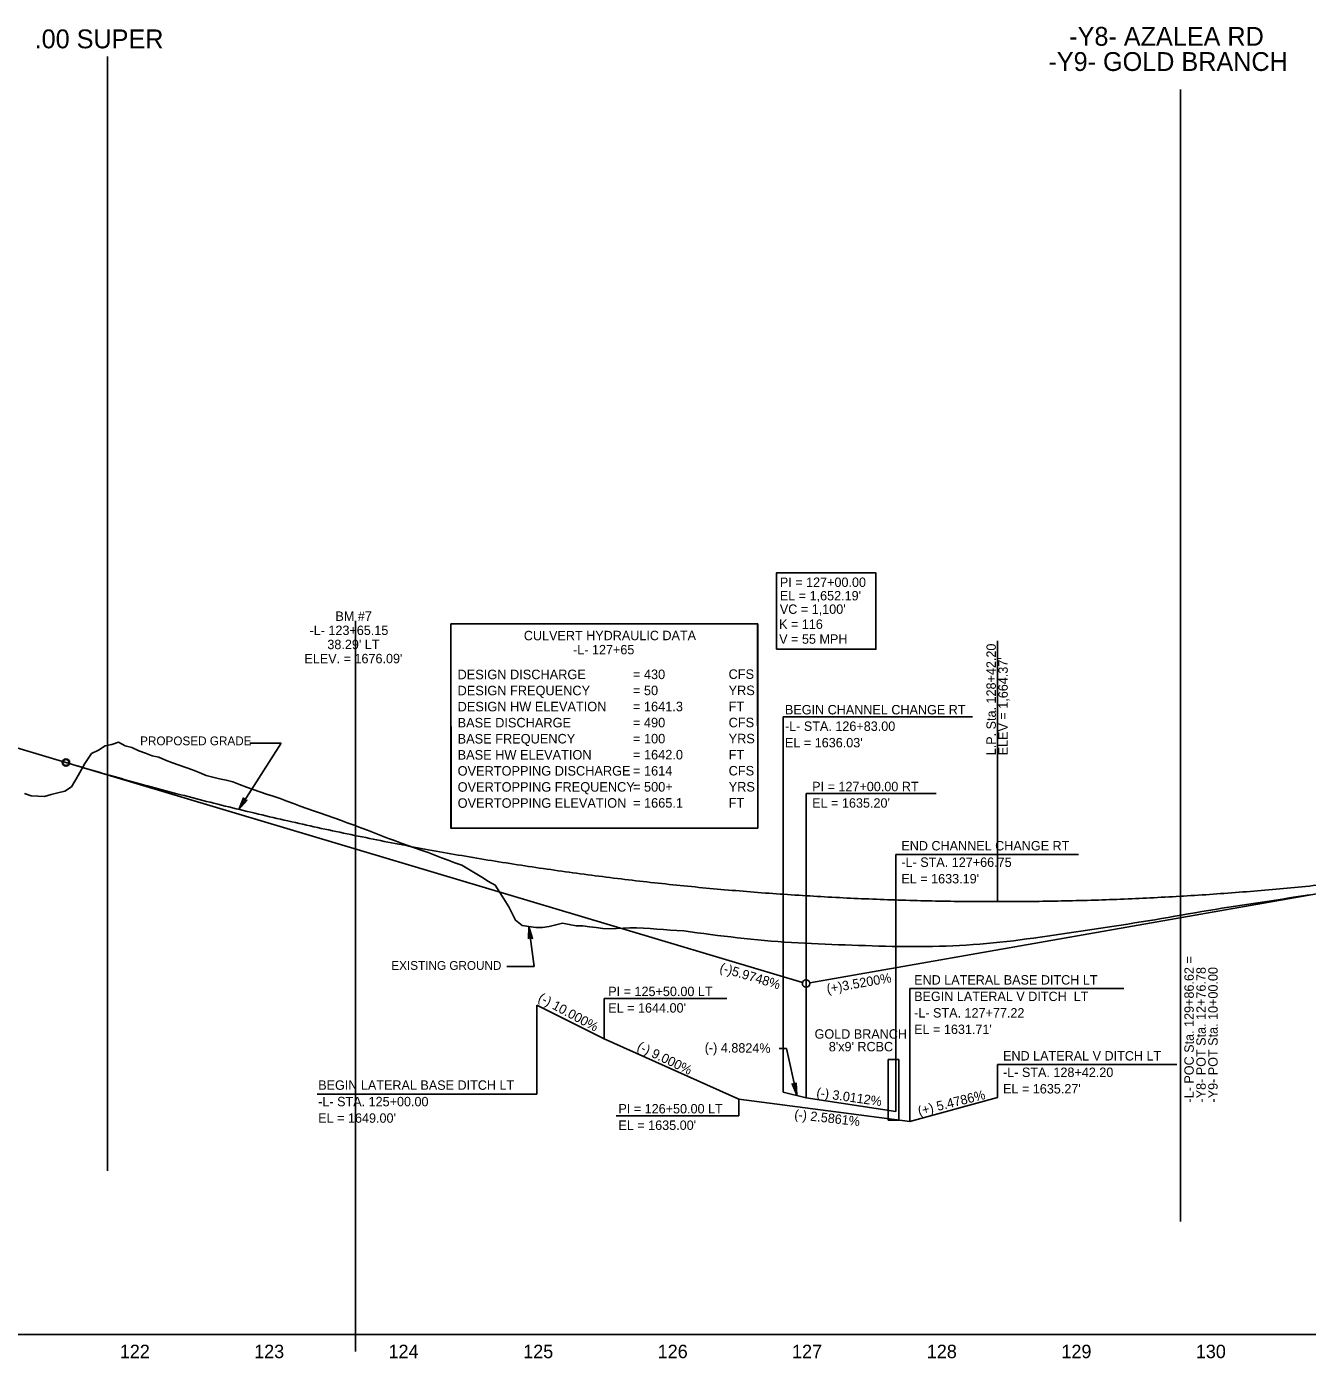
# Model space of a CAD drawing. Extents: x 498575 to 532350, y 405181 to 484585.
# Drawn here: x 516940 to 517892, y 483216 to 484206 of the extents above; entities that cross this region are included whole.
import ezdxf

# ---------------------------------------------------------------- set-up
doc = ezdxf.new("R2010")
doc.units = 0
for name, color, linetype in [('Default', 7, 'Continuous'), ('Exist Profile Cell', 7, 'Continuous'), ('Exist Vertical Profile Ground Line', 7, 'Continuous'), ('Exist Vertical Profile Horizontal Axis Label Major', 7, 'Continuous'), ('Prop Grid Mask', 7, 'Continuous'), ('Prop PFL Text', 7, 'Continuous'), ('Prop Roadway Culvert', 7, 'Continuous'), ('Prop Vertical Profile Curve Label', 7, 'Continuous'), ('Prop Vertical Profile Ditch Grade Left', 7, 'Continuous'), ('Prop Vertical Profile Ditch Grade Left Label', 7, 'Continuous'), ('Prop Vertical Profile Ditch Grade Right', 7, 'Continuous'), ('Prop Vertical Profile Ditch Grade Right Label', 7, 'Continuous'), ('Prop Vertical Profile Grade', 7, 'Continuous'), ('Prop Vertical Profile Grade Label', 7, 'Continuous'), ('Prop Vertical Profile Strip Grade', 7, 'Continuous'), ('Prop VPI Label', 7, 'Continuous'), ('Scratch_Level_0', 7, 'Continuous'), ('Scratch_Level_2', 7, 'Continuous'), ('Scratch_Level_4', 7, 'Continuous')]:
    doc.layers.add(name, color=color, linetype=linetype)

msp = doc.modelspace()

# ---------------------------------------------------------------- linework, layer by layer
at = {"layer": 'Exist Profile Cell'}
msp.add_line((505856.74, 483233.71), (526056.74, 483233.71), dxfattribs=at)
at = {"layer": 'Exist Vertical Profile Ground Line'}
for points in [[(516938.15, 483635.91), (516943.15, 483634.26), (516948.15, 483633.98), (516953.15, 483633.65), (516958.15, 483635.29), (516963.15, 483636.53), (516968.15, 483637.76), (516973.15, 483640.98), (516978.15, 483649.41), (516983.15, 483658.36), (516988.15, 483665.73), (516993.15, 483668.28), (516998.15, 483671.49), (517003.15, 483672.43), (517008.15, 483674.15), (517013.15, 483671.33), (517018.15, 483670.07), (517023.15, 483667.74), (517028.15, 483665.91), (517033.15, 483664.04), (517038.15, 483662.85), (517043.15, 483660.68), (517048.15, 483658.81), (517053.15, 483657.04), (517058.15, 483655.3), (517063.15, 483653.64), (517068.15, 483651.49), (517073.15, 483649.32), (517078.15, 483648.08), (517083.15, 483646.97), (517088.15, 483645.87), (517093.15, 483644.6), (517098.15, 483642.68), (517103.15, 483640.79), (517108.15, 483638.94), (517113.15, 483637.09), (517118.15, 483635.44), (517123.15, 483633.91), (517128.15, 483632.2), (517133.15, 483630.34), (517138.15, 483628.51), (517143.15, 483626.66), (517148.15, 483624.83), (517153.15, 483623.13), (517158.15, 483621.3), (517163.15, 483619.66), (517168.15, 483617.92), (517173.15, 483616.15), (517178.15, 483614.26), (517183.15, 483612.39), (517188.15, 483610.51), (517193.15, 483608.58), (517198.15, 483606.7), (517203.15, 483604.78), (517208.15, 483602.79), (517213.15, 483600.9), (517218.15, 483598.93), (517223.15, 483597.36), (517228.15, 483595.45), (517233.15, 483593.72), (517238.15, 483592.01), (517243.15, 483590.06), (517248.15, 483588.18), (517253.15, 483586.38), (517258.15, 483584.54), (517263.15, 483582.71), (517268.15, 483579.74), (517273.15, 483576.76), (517278.15, 483573.67), (517283.15, 483570.65), (517288.15, 483567.89), (517293.15, 483559.75), (517298.15, 483551.63), (517303.15, 483541.76), (517308.15, 483537.89), (517313.15, 483537)], [(517813.15, 483548.19), (517818.15, 483549.01), (517823.15, 483549.8), (517828.15, 483550.61), (517833.15, 483551.38), (517838.15, 483552.16), (517843.15, 483552.92), (517848.15, 483553.69), (517853.15, 483554.44), (517858.15, 483555.23), (517863.15, 483555.99), (517868.15, 483556.77), (517873.15, 483557.51), (517878.15, 483558.3), (517883.15, 483559.07), (517888.15, 483559.85), (517893.15, 483560.6)], [(517313.15, 483537), (517318.15, 483536.34), (517323.15, 483536.41), (517328.15, 483537.05), (517333.15, 483538.23), (517338.15, 483539.57), (517343.15, 483538.69), (517348.15, 483537.64), (517353.15, 483537.55), (517358.15, 483536.92), (517363.15, 483536.25), (517368.15, 483535.55), (517373.15, 483535.33), (517378.15, 483535.61), (517383.15, 483535.86), (517388.15, 483536.06), (517393.15, 483536.18), (517398.15, 483535.78), (517403.15, 483535.51), (517408.15, 483535.23), (517413.15, 483534.93), (517418.15, 483534.39), (517423.15, 483534.12), (517428.15, 483533.87), (517433.15, 483533.19), (517438.15, 483532.49), (517443.15, 483531.79), (517448.15, 483531.08), (517453.15, 483530.44), (517458.15, 483529.91), (517463.15, 483529.32), (517468.15, 483528.69), (517473.15, 483528.11), (517478.15, 483527.57), (517483.15, 483527.08), (517488.15, 483526.61), (517493.15, 483526.2), (517498.15, 483525.89), (517503.15, 483525.51), (517508.15, 483525.2), (517513.15, 483524.9), (517518.15, 483524.63), (517523.15, 483524.38), (517528.15, 483524.18), (517533.15, 483523.98), (517538.15, 483523.77), (517543.15, 483523.58), (517548.15, 483523.37), (517553.15, 483523.19), (517558.15, 483523.02), (517563.15, 483522.88), (517568.15, 483522.73), (517573.15, 483522.54), (517578.15, 483522.42), (517583.15, 483522.31), (517588.15, 483522.23), (517593.15, 483522.18), (517598.15, 483522.15), (517603.15, 483522.17), (517608.15, 483522.23), (517613.15, 483522.3), (517618.15, 483522.42), (517623.15, 483522.55), (517628.15, 483522.77), (517633.15, 483523.01), (517638.15, 483523.33), (517643.15, 483523.66), (517648.15, 483524.04), (517653.15, 483524.47), (517658.15, 483524.89), (517663.15, 483525.39), (517668.15, 483525.94), (517673.15, 483526.54), (517678.15, 483527.16), (517683.15, 483527.82), (517688.15, 483528.49), (517693.15, 483529.18), (517698.15, 483529.86), (517703.15, 483530.57), (517708.15, 483531.31), (517713.15, 483532.04), (517718.15, 483532.8), (517723.15, 483533.52), (517728.15, 483534.28), (517733.15, 483535.05), (517738.15, 483535.83), (517743.15, 483536.63), (517748.15, 483537.42), (517753.15, 483538.16), (517758.15, 483538.94), (517763.15, 483539.72), (517768.15, 483540.5), (517773.15, 483541.3), (517778.15, 483542.15), (517783.15, 483543), (517788.15, 483543.86), (517793.15, 483544.73), (517798.15, 483545.61), (517803.15, 483546.46), (517808.15, 483547.33), (517813.15, 483548.19)]]:
    msp.add_lwpolyline(points, dxfattribs=at)
at = {"layer": 'Prop Grid Mask'}
for points in [[(517497.03, 483743.2), (517571.01, 483743.2), (517571.01, 483799.98), (517497.03, 483799.98)], [(517255.18, 483762.06), (517483.11, 483762.06), (517483.11, 483610.19), (517255.18, 483610.19)], [(517255.3, 483610.01), (517483.11, 483610.19), (517482.99, 483762.06), (517255.18, 483761.88)]]:
    msp.add_lwpolyline(points, close=True, dxfattribs=at)
at = {"layer": 'Prop PFL Text'}
for p, q in [((517097.6, 483624.14), (517129.13, 483673.33)), ((517129.13, 483673.33), (517105.71, 483673.33)), ((517317.11, 483507.41), (517312.98, 483537.03)), ((517296.75, 483507.41), (517317.11, 483507.41))]:
    msp.add_line(p, q, dxfattribs=at)
for points in [[(517103.71, 483630.92), (517097.6, 483624.14), (517101.07, 483632.65), (517101.81, 483630.82)], [(517312.69, 483527.9), (517312.98, 483537.03), (517315.82, 483528.29), (517314.08, 483529.21)]]:
    msp.add_lwpolyline(points, close=True, dxfattribs=at)
at = {"layer": 'Prop Roadway Culvert'}
for p, q in [((517580.08, 483393.16), (517580.08, 483438.16)), ((517580.08, 483438.16), (517588.08, 483438.16)), ((517588.08, 483393.16), (517588.08, 483438.16)), ((517580.08, 483393.16), (517588.08, 483393.16))]:
    msp.add_line(p, q, dxfattribs=at)
at = {"layer": 'Prop Vertical Profile Curve Label'}
msp.add_circle((516969.08, 483658.97), 2.25, dxfattribs=at)
at = {"layer": 'Prop Vertical Profile Ditch Grade Left'}
msp.add_lwpolyline([(517319.08, 483478.71), (517369.08, 483453.71), (517469.08, 483408.71), (517596.3, 483392.26), (517661.28, 483410.06)], dxfattribs=at)
at = {"layer": 'Prop Vertical Profile Ditch Grade Left Label'}
for p, q in [((517369.08, 483453.71), (517369.08, 483483.62)), ((517460.19, 483483.62), (517369.08, 483483.62)), ((517596.3, 483392.26), (517596.3, 483491.03)), ((517755.25, 483491.03), (517596.3, 483491.03)), ((517319.08, 483478.71), (517319.08, 483412.56)), ((517661.28, 483410.06), (517661.28, 483434.63)), ((517794.7, 483434.63), (517661.28, 483434.63)), ((517155.76, 483412.56), (517319.08, 483412.56)), ((517469.08, 483408.71), (517469.08, 483396.42)), ((517469.08, 483396.42), (517377.96, 483396.42))]:
    msp.add_line(p, q, dxfattribs=at)
at = {"layer": 'Prop Vertical Profile Ditch Grade Right'}
msp.add_lwpolyline([(517502.08, 483413.86), (517519.08, 483409.71), (517585.83, 483399.66)], dxfattribs=at)
at = {"layer": 'Prop Vertical Profile Ditch Grade Right Label'}
for p, q in [((517502.08, 483413.86), (517502.08, 483692.83)), ((517642.75, 483692.83), (517502.08, 483692.83)), ((517519.08, 483409.71), (517519.08, 483635.91)), ((517615.72, 483635.91), (517519.08, 483635.91)), ((517721.5, 483590.68), (517585.83, 483590.68)), ((517585.83, 483399.66), (517585.83, 483590.68)), ((517504.61, 483446.41), (517499.12, 483446.41)), ((517504.61, 483446.41), (517512.1, 483411.64))]:
    msp.add_line(p, q, dxfattribs=at)
msp.add_lwpolyline([(517511.72, 483420.77), (517512.1, 483411.64), (517508.63, 483420.15), (517510.43, 483419.37)], close=True, dxfattribs=at)
at = {"layer": 'Prop Vertical Profile Grade'}
msp.add_line((516294.08, 483860.62), (516969.08, 483658.97), dxfattribs=at)
msp.add_spline([(516969.08, 483658.97), (516991.08, 483652.5), (517013.08, 483646.24), (517035.08, 483640.19), (517057.08, 483634.35), (517079.08, 483628.72), (517101.08, 483623.29), (517123.08, 483618.08), (517145.08, 483613.07), (517167.08, 483608.28), (517189.08, 483603.69), (517211.08, 483599.31), (517233.08, 483595.14), (517255.08, 483591.18), (517277.08, 483587.43), (517299.08, 483583.88), (517321.08, 483580.55), (517343.08, 483577.42), (517365.08, 483574.51), (517387.08, 483571.8), (517409.08, 483569.3), (517431.08, 483567.01), (517453.08, 483564.93), (517475.08, 483563.06), (517497.08, 483561.39), (517519.08, 483559.94), (517541.08, 483558.69), (517563.08, 483557.66), (517585.08, 483556.83), (517607.08, 483556.21), (517629.08, 483555.8), (517651.08, 483555.6), (517673.08, 483555.61), (517695.08, 483555.82), (517717.08, 483556.25), (517739.08, 483556.88), (517761.08, 483557.72), (517783.08, 483558.78), (517805.08, 483560.04), (517827.08, 483561.51), (517849.08, 483563.19), (517871.08, 483565.07), (517893.08, 483567.17), (517915.08, 483569.48), (517937.08, 483571.99), (517959.08, 483574.71), (517981.08, 483577.64), (518003.08, 483580.79), (518025.08, 483584.14), (518047.08, 483587.69), (518069.08, 483591.46)], degree=3, dxfattribs=at)
at = {"layer": 'Prop Vertical Profile Strip Grade'}
for p, q in [((517661.27, 483749.32), (517661.27, 483555.58)), ((517797.36, 483401.96), (517797.36, 483559.57))]:
    msp.add_line(p, q, dxfattribs=at)
at = {"layer": 'Prop VPI Label'}
for p, q in [((516969.08, 483658.97), (517516.44, 483495.45)), ((518069.08, 483591.46), (517521.78, 483495.14))]:
    msp.add_line(p, q, dxfattribs=at)
for centre in [(516969.08, 483658.97), (517519.08, 483494.66)]:
    msp.add_circle(centre, 2.75, dxfattribs=at)
at = {"layer": 'Scratch_Level_0'}
msp.add_line((517184.23, 483221.21), (517184.23, 483764.27), dxfattribs=at)
at = {"layer": 'Scratch_Level_2'}
msp.add_line((517797.36, 484159.22), (517797.36, 483317.76), dxfattribs=at)
at = {"layer": 'Scratch_Level_4'}
msp.add_line((517000.01, 484183.71), (517000.01, 483355.53), dxfattribs=at)

# ---------------------------------------------------------------- texts
at = {"layer": 'Default'}
for s, height, p in [('CULVERT HYDRAULIC DATA', 7, (517309.36, 483749.84)), ('-L- 127+65', 7, (517345.94, 483739.36)), ('DESIGN DISCHARGE', 7.0874, (517260.1, 483720.88)), ('DESIGN DISCHARGE', 7.0874, (517260.1, 483720.88)), ('= 430', 7.087, (517390.41, 483720.98)), ('CFS', 7.087, (517461.49, 483721.14)), ('DESIGN FREQUENCY', 7.0874, (517260.11, 483708.93)), ('DESIGN FREQUENCY', 7.0874, (517260.11, 483708.93)), ('= 50', 7.087, (517390.42, 483709.04)), ('YRS', 7.087, (517461.5, 483709.09)), ('DESIGN HW ELEVATION', 7.0874, (517260.12, 483696.99)), ('DESIGN HW ELEVATION', 7.0874, (517260.12, 483696.99)), ('= 1641.3', 7.087, (517390.43, 483697.09)), ('FT', 7.087, (517461.51, 483697.14)), ('BASE DISCHARGE', 7.0874, (517260.13, 483685.04)), ('BASE DISCHARGE', 7.0874, (517260.13, 483685.04)), ('= 490', 7.087, (517390.44, 483685.14)), ('CFS', 7.087, (517461.52, 483685.2)), ('BASE FREQUENCY', 7.0874, (517260.14, 483673.09)), ('BASE FREQUENCY', 7.0874, (517260.14, 483673.09)), ('= 100', 7.087, (517390.45, 483673.19)), ('YRS', 7.087, (517461.53, 483673.25)), ('BASE HW ELEVATION', 7.0874, (517260.15, 483661.14)), ('BASE HW ELEVATION', 7.0874, (517260.15, 483661.14)), ('= 1642.0', 7.087, (517390.46, 483661.25)), ('FT', 7.087, (517461.54, 483661.3)), ('OVERTOPPING DISCHARGE', 7.0874, (517260.16, 483649.2)), ('= 1614', 7.087, (517390.47, 483649.3)), ('CFS', 7.087, (517461.55, 483649.35)), ('OVERTOPPING FREQUENCY', 7.0874, (517260.17, 483637.25)), ('= 500+', 7.087, (517390.48, 483637.35)), ('YRS', 7.087, (517461.56, 483637.41)), ('OVERTOPPING ELEVATION', 7.0874, (517260.18, 483625.3)), ('= 1665.1', 7.087, (517390.49, 483625.4)), ('FT', 7.087, (517461.57, 483625.46))]:
    msp.add_text(s, height=height, rotation=0.0449, dxfattribs=at).set_placement(p)
for s, p in [('GOLD BRANCH', (517525.42, 483453.71)), ("8'x9' RCBC", (517535.97, 483444.29))]:
    msp.add_text(s, height=7, dxfattribs=at).set_placement(p)
at = {"layer": 'Exist Vertical Profile Horizontal Axis Label Major'}
for s, p in [('122', (517009.09, 483216.21)), ('122', (517009.1, 483216.21)), ('123', (517108.93, 483216.21)), ('123', (517108.93, 483216.21)), ('124', (517208.77, 483216.21)), ('124', (517208.77, 483216.21)), ('125', (517308.87, 483216.21)), ('125', (517308.86, 483216.21)), ('126', (517408.8, 483216.21)), ('126', (517408.81, 483216.21)), ('127', (517508.66, 483216.21)), ('127', (517508.66, 483216.21)), ('128', (517608.79, 483216.21)), ('128', (517608.79, 483216.21)), ('129', (517708.83, 483216.21)), ('129', (517708.83, 483216.21)), ('130', (517808.7, 483216.21)), ('130', (517808.71, 483216.21))]:
    msp.add_text(s, height=10, dxfattribs=at).set_placement(p)
at = {"layer": 'Prop PFL Text'}
for s, height, p in [('BM #7', 7, (517169.34, 483764.27)), ('-L- 123+65.15', 7, (517150.09, 483753.77)), ("38.29' LT", 7, (517163.34, 483743.27)), ("ELEV. = 1676.09'", 7, (517146.28, 483732.77)), ('PROPOSED GRADE', 6.5157, (517024.19, 483671.83)), ('EXISTING GROUND', 6.5157, (517210.88, 483504.86))]:
    msp.add_text(s, height=height, dxfattribs=at).set_placement(p)
at = {"layer": 'Prop Vertical Profile Curve Label'}
for s, p in [('PI = 127+00.00', (517499.58, 483789.49)), ("EL = 1,652.19'", (517499.58, 483779.49)), ("VC = 1,100'", (517499.58, 483769.49)), ('K = 116', (517499.02, 483758.34)), ('V = 55 MPH ', (517499.1, 483747.27))]:
    msp.add_text(s, height=7, dxfattribs=at).set_placement(p)
at = {"layer": 'Prop Vertical Profile Ditch Grade Left Label'}
for s, rotation, p in [('END LATERAL BASE DITCH LT', 360, (517599.39, 483493.92)), ('(-) 10.000%', 331.4841, (517319.32, 483482.02)), ('PI = 125+50.00 LT', 360, (517372.08, 483485.35)), ('BEGIN LATERAL V DITCH  LT', 360, (517599.39, 483481.67)), ("EL = 1644.00'", 360, (517372.08, 483473.1)), ('-L- STA. 127+77.22', 360, (517599.39, 483469.42)), ("EL = 1631.71'", 360, (517599.39, 483457.17)), ('(-) 9.000%', 334.26485, (517392.84, 483445.56)), ('END LATERAL V DITCH LT', 360, (517665.45, 483437.47)), ('-L- STA. 128+42.20', 360, (517665.45, 483425.22)), ('BEGIN LATERAL BASE DITCH LT', 360, (517156.54, 483415.7)), ('(+) 5.4786%', 14.16267, (517603.14, 483396.43)), ("EL = 1635.27'", 360, (517665.45, 483412.97)), ('-L- STA. 125+00.00', 360, (517156.54, 483403.45)), ('PI = 126+50.00 LT', 360, (517379.62, 483398.14)), ("EL = 1649.00'", 360, (517156.54, 483391.2)), ('(-) 2.5861%', 353.52962, (517510.08, 483394.14)), ("EL = 1635.00'", 360, (517379.62, 483385.89))]:
    msp.add_text(s, height=7, rotation=rotation, dxfattribs=at).set_placement(p)
at = {"layer": 'Prop Vertical Profile Ditch Grade Right Label'}
for s, rotation, p in [('BEGIN CHANNEL CHANGE RT', 360, (517503.39, 483694.75)), ('-L- STA. 126+83.00', 360, (517503.39, 483682.5)), ("EL = 1636.03'", 360, (517503.39, 483670.25)), ('PI = 127+00.00 RT', 360, (517523.62, 483637.66)), ("EL = 1635.20'", 360, (517523.62, 483625.41)), ('END CHANNEL CHANGE RT', 360, (517589.9, 483593.63)), ('-L- STA. 127+66.75', 360, (517589.9, 483581.38)), ("EL = 1633.19'", 360, (517589.9, 483569.13)), ('(-) 4.8824%', 359.46319, (517443.75, 483443.6)), ('(-) 3.0112%', 351.91965, (517526.44, 483410.39))]:
    msp.add_text(s, height=7, rotation=rotation, dxfattribs=at).set_placement(p)
at = {"layer": 'Prop Vertical Profile Grade Label'}
for s, rotation, p in [('(-)5.9748%', 343.36711, (517454.34, 483503.57)), ('(+)3.5200%', 9.98183, (517535.02, 483487.31))]:
    msp.add_text(s, height=7, rotation=rotation, dxfattribs=at).set_placement(p)
at = {"layer": 'Prop Vertical Profile Strip Grade'}
for s, p in [('L.P. Sta. 128+42.20', (517660.1, 483664.37)), ("ELEV = 1,664.37'", (517668.97, 483664.37)), ('-L- POC Sta. 129+86.62 = ', (517807.2, 483406.27)), ('-Y8- POT Sta. 12+76.78', (517816.08, 483406.27)), ('-Y9- POT Sta. 10+00.00', (517824.95, 483406.27))]:
    msp.add_text(s, height=7, rotation=90, dxfattribs=at).set_placement(p)
at = {"layer": 'Scratch_Level_2'}
for s, p in [('-Y8- AZALEA RD', (517714.64, 484191.79)), ('-Y9- GOLD BRANCH', (517699.19, 484173.06))]:
    msp.add_text(s, height=14, dxfattribs=at).set_placement(p)
at = {"layer": 'Scratch_Level_4'}
msp.add_text('.00 SUPER', height=14, dxfattribs=at).set_placement((516945.81, 484189.9))

doc.saveas('drawing.dxf')
